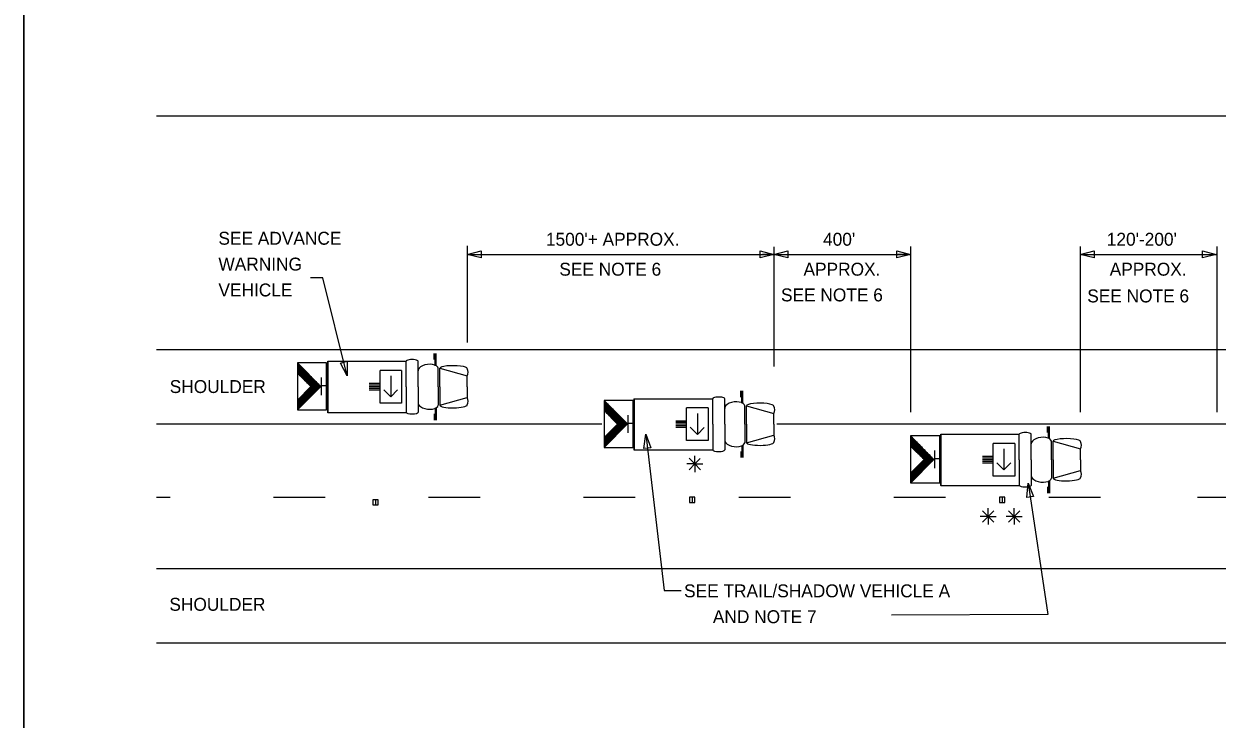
# Model space of a CAD drawing. Extents: x 1416408 to 1429341, y 372694 to 383211.
# Drawn here: x 1426235 to 1427162, y 373399 to 373939 of the extents above; entities that cross this region are included whole.
import ezdxf

# ---------------------------------------------------------------- set-up
doc = ezdxf.new("R2010")
doc.units = 0
for name, color, linetype in [('Default', 7, 'Continuous'), ('DSN_DRFT_Junk-No-Plot', 7, 'Continuous'), ('Level 1', 7, 'Continuous'), ('Working Level 1', 7, 'Continuous')]:
    doc.layers.add(name, color=color, linetype=linetype)

msp = doc.modelspace()

# ---------------------------------------------------------------- linework, layer by layer
at = {"layer": 'Default'}
for points in [[(1426234.86, 374479.9), (1426234.86, 372693.86), (1428995.11, 372693.86), (1428995.11, 374479.9)], [(1426234.86, 374479.9), (1426234.86, 372693.86), (1428995.11, 372693.86), (1428995.11, 374479.9)], [(1426234.86, 374479.9), (1428995.11, 374479.9), (1428995.11, 372693.86), (1426234.86, 372693.86)], [(1426234.86, 374479.9), (1426234.86, 372693.86), (1428995.11, 372693.86), (1428995.11, 374479.9)]]:
    msp.add_lwpolyline(points, close=True, dxfattribs=at)
at = {"layer": 'DSN_DRFT_Junk-No-Plot'}
msp.add_lwpolyline([(1426234.86, 374479.9), (1428995.11, 374479.9), (1428995.11, 372693.86), (1426234.86, 372693.86)], close=True, dxfattribs=at)
at = {"layer": 'Level 1'}
msp.add_lwpolyline([(1427015.28, 373582.25), (1427030.51, 373480.04), (1426909.15, 373479.57)], dxfattribs=at)
at = {"layer": 'Working Level 1'}
for p, q in [((1426337.99, 373867.74), (1427662.99, 373867.74)), ((1426579.46, 373766.82), (1426579.46, 373691.51)), ((1426817.73, 373765.82), (1426817.73, 373672.98)), ((1426923.95, 373766.22), (1426923.95, 373637.48)), ((1427055.68, 373766.22), (1427055.68, 373637.48)), ((1427161.91, 373766.22), (1427161.91, 373637.48)), ((1426579.46, 373760.03), (1426588.68, 373760.03)), ((1426579.46, 373760.03), (1426817.73, 373760.03)), ((1426817.73, 373760.03), (1426808.97, 373760.03)), ((1426817.73, 373760.03), (1426827.96, 373760.03)), ((1426817.73, 373760.03), (1426923.95, 373760.03)), ((1426922.75, 373760.03), (1426913.99, 373760.03)), ((1427055.68, 373760.03), (1427065.92, 373760.03)), ((1427055.68, 373760.03), (1427161.91, 373760.03)), ((1426337.99, 373686), (1427662.99, 373686)), ((1426553.8, 373678.2), (1426553.8, 373683.07)), ((1426554.56, 373673.51), (1426554.56, 373683.07)), ((1426555.21, 373673.51), (1426555.21, 373683.07)), ((1426447.43, 373675.71), (1426465.57, 373657.38)), ((1426470.79, 373676.56), (1426470.79, 373636.76)), ((1426470.95, 373677.02), (1426470.95, 373637.22)), ((1426470.95, 373637.21), (1426470.95, 373677.01)), ((1426470.95, 373677.01), (1426531.88, 373677.01)), ((1426531.88, 373657.11), (1426531.88, 373677.01)), ((1426541.21, 373657.11), (1426541.21, 373677.01)), ((1426447.43, 373667.75), (1426457.83, 373657.27)), ((1426466.18, 373650.48), (1426466.18, 373664.28)), ((1426528.3, 373669.85), (1426511.65, 373669.85)), ((1426511.65, 373644.37), (1426511.65, 373669.85)), ((1426519.98, 373665.52), (1426519.98, 373649.23)), ((1426528.3, 373669.85), (1426528.3, 373644.37)), ((1426556.86, 373657.11), (1426556.86, 373671.45)), ((1426558.16, 373671.45), (1426579.46, 373665.55)), ((1426558.16, 373657.11), (1426558.16, 373671.45)), ((1426579.46, 373657.11), (1426579.46, 373665.55)), ((1426447.43, 373646.78), (1426457.83, 373657.27)), ((1426447.53, 373639.13), (1426465.57, 373657.38)), ((1426469.98, 373657.71), (1426466.08, 373657.71)), ((1426511.65, 373659.65), (1426503.16, 373659.65)), ((1426511.65, 373658.38), (1426503.16, 373658.38)), ((1426511.65, 373657.1), (1426503.16, 373657.1)), ((1426511.65, 373655.83), (1426503.16, 373655.83)), ((1426511.65, 373654.56), (1426503.16, 373654.56)), ((1426519.98, 373649.23), (1426514.5, 373654.77)), ((1426519.98, 373649.23), (1426525.33, 373654.63)), ((1426531.88, 373657.11), (1426531.88, 373637.22)), ((1426541.21, 373657.11), (1426541.21, 373637.22)), ((1426556.86, 373657.11), (1426556.86, 373642.78)), ((1426558.16, 373657.11), (1426558.16, 373642.78)), ((1426579.46, 373657.11), (1426579.46, 373648.67)), ((1426792.06, 373649.04), (1426792.06, 373653.92)), ((1426792.83, 373644.36), (1426792.83, 373653.92)), ((1426793.48, 373644.36), (1426793.48, 373653.92)), ((1426528.3, 373644.37), (1426511.65, 373644.37)), ((1426558.16, 373642.78), (1426579.46, 373648.67)), ((1426685.69, 373646.56), (1426703.84, 373628.23)), ((1426709.05, 373647.4), (1426709.05, 373607.6)), ((1426709.21, 373647.86), (1426709.21, 373608.06)), ((1426709.21, 373608.05), (1426709.21, 373647.85)), ((1426709.21, 373647.85), (1426770.14, 373647.85)), ((1426770.14, 373627.96), (1426770.14, 373647.85)), ((1426779.48, 373627.96), (1426779.48, 373647.85)), ((1426470.95, 373637.22), (1426531.88, 373637.22)), ((1426553.8, 373636.02), (1426553.8, 373631.15)), ((1426554.56, 373640.71), (1426554.56, 373631.15)), ((1426555.21, 373640.71), (1426555.21, 373631.15)), ((1426685.69, 373638.6), (1426696.09, 373628.11)), ((1426704.45, 373621.33), (1426704.45, 373635.13)), ((1426766.57, 373640.69), (1426749.91, 373640.69)), ((1426749.91, 373615.22), (1426749.91, 373640.69)), ((1426758.24, 373636.37), (1426758.24, 373620.07)), ((1426766.57, 373640.69), (1426766.57, 373615.22)), ((1426795.12, 373627.96), (1426795.12, 373642.29)), ((1426796.42, 373642.29), (1426817.72, 373636.4)), ((1426796.42, 373627.96), (1426796.42, 373642.29)), ((1426817.72, 373627.96), (1426817.72, 373636.4)), ((1426337.99, 373628.26), (1426580.23, 373628.26)), ((1426579.86, 373628.26), (1426684.12, 373628.26)), ((1426685.69, 373617.63), (1426696.09, 373628.11)), ((1426685.79, 373609.97), (1426703.84, 373628.23)), ((1426708.24, 373628.56), (1426704.34, 373628.56)), ((1426749.91, 373630.49), (1426741.43, 373630.49)), ((1426749.91, 373629.22), (1426741.43, 373629.22)), ((1426749.91, 373627.95), (1426741.43, 373627.95)), ((1426749.91, 373626.68), (1426741.43, 373626.68)), ((1426758.24, 373620.07), (1426752.76, 373625.61)), ((1426770.14, 373627.96), (1426770.14, 373608.06)), ((1426779.48, 373627.96), (1426779.48, 373608.06)), ((1426795.12, 373627.96), (1426795.12, 373613.62)), ((1426796.42, 373627.96), (1426796.42, 373613.62)), ((1426817.72, 373627.96), (1426817.72, 373619.51)), ((1426819.89, 373628.26), (1427662.99, 373628.26)), ((1427030.33, 373621.45), (1427030.33, 373626.33)), ((1427031.09, 373616.77), (1427031.09, 373626.33)), ((1427031.74, 373616.77), (1427031.74, 373626.33)), ((1426749.91, 373625.41), (1426741.43, 373625.41)), ((1426758.24, 373620.07), (1426763.59, 373625.48)), ((1426796.42, 373613.62), (1426817.72, 373619.51)), ((1426923.95, 373618.97), (1426942.1, 373600.64)), ((1426947.32, 373619.81), (1426947.32, 373580.01)), ((1426947.47, 373620.27), (1426947.47, 373580.47)), ((1426947.47, 373580.46), (1426947.47, 373620.26)), ((1426947.47, 373620.26), (1427008.41, 373620.26)), ((1427008.41, 373600.37), (1427008.41, 373620.26)), ((1427017.74, 373600.37), (1427017.74, 373620.26)), ((1426709.21, 373608.06), (1426770.14, 373608.06)), ((1426766.57, 373615.22), (1426749.91, 373615.22)), ((1426792.83, 373611.56), (1426792.83, 373602)), ((1426793.48, 373611.56), (1426793.48, 373602)), ((1426923.95, 373611.01), (1426934.36, 373600.52)), ((1426942.71, 373593.74), (1426942.71, 373607.54)), ((1427004.83, 373613.1), (1426988.18, 373613.1)), ((1426988.18, 373587.62), (1426988.18, 373613.1)), ((1426996.5, 373608.78), (1426996.5, 373592.48)), ((1427004.83, 373613.1), (1427004.83, 373587.62)), ((1427033.39, 373600.37), (1427033.39, 373614.7)), ((1427034.68, 373614.7), (1427055.99, 373608.81)), ((1427034.68, 373600.37), (1427034.68, 373614.7)), ((1427055.99, 373600.37), (1427055.99, 373608.81)), ((1426756.17, 373597.09), (1426751.77, 373601.54)), ((1426756.07, 373597), (1426760.48, 373601.46)), ((1426756.17, 373597.09), (1426756.17, 373603.39)), ((1426792.06, 373606.86), (1426792.06, 373602)), ((1426923.95, 373590.04), (1426934.36, 373600.52)), ((1426924.05, 373582.38), (1426942.1, 373600.64)), ((1426946.51, 373600.96), (1426942.6, 373600.96)), ((1426988.18, 373602.9), (1426979.69, 373602.9)), ((1426988.18, 373601.63), (1426979.69, 373601.63)), ((1426988.18, 373600.36), (1426979.69, 373600.36)), ((1426988.18, 373599.09), (1426979.69, 373599.09)), ((1426988.18, 373597.81), (1426979.69, 373597.81)), ((1426996.5, 373592.48), (1426991.02, 373598.02)), ((1426996.5, 373592.48), (1427001.85, 373597.89)), ((1427008.41, 373600.37), (1427008.41, 373580.47)), ((1427017.74, 373600.37), (1427017.74, 373580.47)), ((1427033.39, 373600.37), (1427033.39, 373586.03)), ((1427034.68, 373600.37), (1427034.68, 373586.03)), ((1427055.99, 373600.37), (1427055.99, 373591.92)), ((1426756.17, 373597.09), (1426749.94, 373597.09)), ((1426756.17, 373597.09), (1426751.77, 373592.63)), ((1426756.17, 373597.09), (1426760.58, 373592.63)), ((1426756.17, 373597.09), (1426756.17, 373590.79)), ((1426756.17, 373597.09), (1426762.4, 373597.09)), ((1427034.68, 373586.03), (1427055.99, 373591.92)), ((1426947.47, 373580.47), (1427008.41, 373580.47)), ((1427004.83, 373587.62), (1426988.18, 373587.62)), ((1427030.33, 373579.27), (1427030.33, 373574.41)), ((1427031.09, 373583.96), (1427031.09, 373574.41)), ((1427031.74, 373583.96), (1427031.74, 373574.41)), ((1426752.12, 373571.3), (1426752.11, 373567.23)), ((1426756.14, 373571.3), (1426752.12, 373571.3)), ((1426754.14, 373571.3), (1426754.13, 373567.23)), ((1426756.14, 373567.23), (1426756.14, 373571.3)), ((1426993.05, 373571.3), (1426993.04, 373567.23)), ((1426997.07, 373571.3), (1426993.05, 373571.3)), ((1426995.07, 373571.3), (1426995.06, 373567.23)), ((1426997.07, 373567.23), (1426997.07, 373571.3)), ((1426506.12, 373569.27), (1426506.11, 373565.2)), ((1426506.11, 373565.2), (1426510.13, 373565.2)), ((1426510.13, 373569.27), (1426506.12, 373569.27)), ((1426508.13, 373569.27), (1426508.12, 373565.2)), ((1426510.13, 373565.2), (1426510.13, 373569.27)), ((1426752.11, 373567.23), (1426756.14, 373567.23)), ((1426984.25, 373556.31), (1426979.84, 373560.76)), ((1426984.25, 373556.31), (1426984.25, 373562.61)), ((1426993.04, 373567.23), (1426997.07, 373567.23)), ((1427004.41, 373556.31), (1427000, 373560.76)), ((1427004.41, 373556.31), (1427004.41, 373562.61)), ((1426984.25, 373556.31), (1426978.01, 373556.31)), ((1426984.25, 373556.31), (1426979.84, 373551.85)), ((1426984.14, 373556.22), (1426988.56, 373560.68)), ((1426984.25, 373556.31), (1426988.66, 373551.85)), ((1426984.25, 373556.31), (1426984.25, 373550.01)), ((1426984.25, 373556.31), (1426990.48, 373556.31)), ((1427004.41, 373556.31), (1426998.17, 373556.31)), ((1427004.41, 373556.31), (1427000, 373551.85)), ((1427004.3, 373556.22), (1427008.71, 373560.68)), ((1427004.41, 373556.31), (1427008.81, 373551.85)), ((1427004.41, 373556.31), (1427004.41, 373550.01)), ((1427004.41, 373556.31), (1427010.64, 373556.31)), ((1426337.99, 373515.71), (1427411.75, 373515.71)), ((1426337.99, 373457.97), (1427350.68, 373457.97))]:
    msp.add_line(p, q, dxfattribs=at)
for points in [[(1426590.21, 373757.31), (1426579.44, 373760.03), (1426590.21, 373762.75)], [(1426806.96, 373762.75), (1426817.73, 373760.03), (1426806.96, 373757.31)], [(1426828.49, 373757.31), (1426817.73, 373760.03), (1426828.49, 373762.75)], [(1426913.19, 373762.75), (1426923.95, 373760.03), (1426913.19, 373757.31)], [(1427066.45, 373757.31), (1427055.68, 373760.03), (1427066.45, 373762.75)], [(1427150.7, 373762.75), (1427161.46, 373760.03), (1427150.7, 373757.31)], [(1426447.43, 373675.71), (1426447.43, 373639.12), (1426470.05, 373639.12), (1426470.05, 373675.71)], [(1426486.18, 373676.92), (1426486.22, 373665.7), (1426480.96, 373675.58)], [(1426685.69, 373646.56), (1426685.69, 373609.96), (1426708.31, 373609.96), (1426708.31, 373646.56)], [(1426716.75, 373609.03), (1426718.15, 373620.16), (1426722.1, 373609.67)], [(1426923.95, 373618.97), (1426923.95, 373582.37), (1426946.57, 373582.37), (1426946.57, 373618.97)], [(1427014.23, 373571.09), (1427015.28, 373582.25), (1427019.55, 373571.9)]]:
    msp.add_lwpolyline(points, close=True, dxfattribs=at)
for points in [[(1426486.22, 373665.7), (1426467.12, 373741.78), (1426457.57, 373741.78)], [(1426447.43, 373674.85), (1426457, 373658.09)], [(1426447.43, 373673.41), (1426455.11, 373659.96)], [(1426447.43, 373671.97), (1426453.21, 373661.84)], [(1426448.24, 373674.91), (1426460.91, 373652.69)], [(1426450.17, 373672.93), (1426461.44, 373653.21)], [(1426447.43, 373670.53), (1426451.32, 373663.72)], [(1426447.43, 373669.08), (1426449.43, 373665.6)], [(1426447.43, 373667.64), (1426447.53, 373667.48)], [(1426452.12, 373670.98), (1426461.96, 373653.75)], [(1426454.07, 373669), (1426462.48, 373654.26)], [(1426456.01, 373667.04), (1426463, 373654.8)], [(1426457.95, 373665.06), (1426463.55, 373655.29)], [(1426459.9, 373663.1), (1426464.08, 373655.79)], [(1426454.46, 373653.89), (1426457.25, 373649.01)], [(1426454.98, 373654.4), (1426457.78, 373649.53)], [(1426455.51, 373654.95), (1426458.3, 373650.06)], [(1426456.03, 373655.47), (1426458.82, 373650.59)], [(1426456.56, 373655.99), (1426459.34, 373651.11)], [(1426457.07, 373656.53), (1426459.88, 373651.64)], [(1426457.61, 373657.05), (1426460.4, 373652.16)], [(1426461.86, 373661.16), (1426464.56, 373656.4)], [(1426463.65, 373659.36), (1426465.05, 373656.91)], [(1426447.43, 373646.01), (1426449.93, 373641.63)], [(1426447.43, 373644.56), (1426449.4, 373641.1)], [(1426447.67, 373647.03), (1426450.45, 373642.17)], [(1426448.2, 373647.56), (1426450.98, 373642.68)], [(1426448.72, 373648.08), (1426451.49, 373643.21)], [(1426449.25, 373648.62), (1426452.02, 373643.73)], [(1426449.76, 373649.14), (1426452.54, 373644.27)], [(1426450.29, 373649.66), (1426453.06, 373644.79)], [(1426450.8, 373650.19), (1426453.59, 373645.31)], [(1426451.33, 373650.72), (1426454.12, 373645.84)], [(1426451.86, 373651.25), (1426454.63, 373646.36)], [(1426452.38, 373651.78), (1426455.16, 373646.9)], [(1426452.9, 373652.31), (1426455.68, 373647.42)], [(1426453.41, 373652.83), (1426456.2, 373647.95)], [(1426453.95, 373653.36), (1426456.74, 373648.46)], [(1426685.69, 373645.7), (1426695.27, 373628.93)], [(1426685.69, 373644.26), (1426693.37, 373630.8)], [(1426686.5, 373645.75), (1426699.17, 373623.53)], [(1426447.43, 373643.12), (1426448.88, 373640.58)], [(1426447.43, 373641.67), (1426448.36, 373640.05)], [(1426447.43, 373640.23), (1426447.83, 373639.54)], [(1426685.69, 373642.82), (1426691.48, 373632.68)], [(1426685.69, 373641.37), (1426689.58, 373634.57)], [(1426685.69, 373639.93), (1426687.69, 373636.45)], [(1426685.69, 373638.48), (1426685.79, 373638.33)], [(1426688.43, 373643.78), (1426699.7, 373624.06)], [(1426690.38, 373641.82), (1426700.23, 373624.59)], [(1426692.33, 373639.85), (1426700.74, 373625.11)], [(1426694.27, 373637.88), (1426701.26, 373625.64)], [(1426696.22, 373635.91), (1426701.81, 373626.14)], [(1426693.77, 373625.79), (1426696.57, 373620.9)], [(1426694.29, 373626.32), (1426697.08, 373621.43)], [(1426694.82, 373626.83), (1426697.6, 373621.95)], [(1426695.33, 373627.37), (1426698.14, 373622.48)], [(1426695.87, 373627.9), (1426698.66, 373623.01)], [(1426698.16, 373633.95), (1426702.34, 373626.64)], [(1426700.12, 373632), (1426702.82, 373627.24)], [(1426701.91, 373630.2), (1426703.31, 373627.75)], [(1426685.69, 373616.86), (1426688.19, 373612.47)], [(1426685.93, 373617.87), (1426688.71, 373613.02)], [(1426686.46, 373618.41), (1426689.24, 373613.52)], [(1426686.98, 373618.92), (1426689.75, 373614.06)], [(1426687.51, 373619.47), (1426690.28, 373614.58)], [(1426688.02, 373619.98), (1426690.8, 373615.12)], [(1426688.55, 373620.51), (1426691.32, 373615.63)], [(1426689.07, 373621.03), (1426691.85, 373616.16)], [(1426689.59, 373621.57), (1426692.38, 373616.68)], [(1426690.12, 373622.09), (1426692.9, 373617.21)], [(1426690.64, 373622.62), (1426693.42, 373617.74)], [(1426691.16, 373623.16), (1426693.94, 373618.27)], [(1426691.67, 373623.67), (1426694.46, 373618.79)], [(1426692.21, 373624.21), (1426695, 373619.31)], [(1426692.73, 373624.73), (1426695.51, 373619.85)], [(1426693.25, 373625.25), (1426696.04, 373620.38)], [(1426718.15, 373620.16), (1426732.44, 373498.61), (1426745.53, 373498.61)], [(1426923.95, 373618.1), (1426933.53, 373601.34)], [(1426923.95, 373616.67), (1426931.63, 373603.21)], [(1426924.76, 373618.16), (1426937.43, 373595.94)], [(1426685.69, 373615.4), (1426687.66, 373611.95)], [(1426685.69, 373613.97), (1426687.14, 373611.42)], [(1426685.69, 373612.52), (1426686.62, 373610.9)], [(1426685.69, 373611.08), (1426686.09, 373610.38)], [(1426923.95, 373615.22), (1426929.74, 373605.09)], [(1426923.95, 373613.78), (1426927.84, 373606.98)], [(1426923.95, 373612.34), (1426925.95, 373608.86)], [(1426923.95, 373610.89), (1426924.05, 373610.74)], [(1426926.7, 373616.18), (1426937.96, 373596.47)], [(1426928.64, 373614.23), (1426938.49, 373597)], [(1426930.59, 373612.25), (1426939.01, 373597.52)], [(1426932.53, 373610.29), (1426939.53, 373598.05)], [(1426934.48, 373608.32), (1426940.07, 373598.54)], [(1426932.04, 373598.2), (1426934.83, 373593.31)], [(1426932.56, 373598.72), (1426935.35, 373593.84)], [(1426933.08, 373599.24), (1426935.87, 373594.36)], [(1426933.59, 373599.78), (1426936.4, 373594.89)], [(1426934.13, 373600.31), (1426936.92, 373595.42)], [(1426936.43, 373606.36), (1426940.61, 373599.04)], [(1426938.38, 373604.41), (1426941.08, 373599.65)], [(1426940.18, 373602.61), (1426941.57, 373600.16)], [(1426923.95, 373589.27), (1426926.45, 373584.88)], [(1426924.2, 373590.28), (1426926.97, 373585.43)], [(1426924.72, 373590.82), (1426927.5, 373585.93)], [(1426925.24, 373591.33), (1426928.01, 373586.47)], [(1426925.77, 373591.87), (1426928.55, 373586.98)], [(1426926.28, 373592.39), (1426929.07, 373587.53)], [(1426926.81, 373592.92), (1426929.59, 373588.04)], [(1426927.33, 373593.44), (1426930.11, 373588.57)], [(1426927.86, 373593.97), (1426930.64, 373589.09)], [(1426928.38, 373594.5), (1426931.16, 373589.62)], [(1426928.9, 373595.03), (1426931.69, 373590.15)], [(1426929.42, 373595.57), (1426932.21, 373590.68)], [(1426929.93, 373596.08), (1426932.73, 373591.2)], [(1426930.47, 373596.62), (1426933.26, 373591.72)], [(1426930.99, 373597.14), (1426933.77, 373592.26)], [(1426931.51, 373597.66), (1426934.3, 373592.78)], [(1426923.95, 373587.81), (1426925.93, 373584.36)], [(1426923.95, 373586.38), (1426925.41, 373583.83)], [(1426923.95, 373584.92), (1426924.89, 373583.31)], [(1426923.95, 373583.49), (1426924.35, 373582.79)], [(1426337.99, 373571.35), (1426348.54, 373571.35)], [(1426428.86, 373571.35), (1426469.03, 373571.35)], [(1426549.35, 373571.35), (1426589.51, 373571.35)], [(1426669.84, 373571.35), (1426710.01, 373571.35)], [(1426790.33, 373571.35), (1426830.5, 373571.35)], [(1426910.82, 373571.35), (1426950.99, 373571.35)], [(1427031.31, 373571.35), (1427071.48, 373571.35)], [(1427146.83, 373571.35), (1427187, 373571.35)]]:
    msp.add_lwpolyline(points, dxfattribs=at)
for centre, major_axis, ratio, start_param, end_param in [((1426536.55, 373677.01), (4.67, 0), 0.27289, 6.283185, 9.424778), ((1426549.04, 373670.47), (7.82, 0.99), 0.50847, 6.28135, 9.422943), ((1426568.81, 373671.32), (10.65, -0.12), 0.205643, 0.000054, 3.141647), ((1426574.25, 373668.37), (0, 5.98), 0.989089, 4.221603, 5.203174), ((1426549.04, 373643.76), (7.82, -0.99), 0.50847, 3.143427, 6.28502), ((1426574.25, 373645.85), (0, 5.98), 0.989089, 4.221604, 5.203174), ((1426774.81, 373647.85), (4.67, 0), 0.27289, 6.283185, 9.424778), ((1426787.3, 373641.31), (7.82, 0.99), 0.50847, 6.28135, 9.422943), ((1426807.07, 373642.17), (10.65, -0.12), 0.205643, 0.000054, 3.141647), ((1426536.55, 373637.22), (4.67, 0), 0.27289, 3.141593, 6.283185), ((1426568.81, 373642.9), (10.65, 0.12), 0.205643, 3.141539, 6.283131), ((1426812.51, 373639.22), (0, 5.98), 0.989089, 4.221603, 5.203174), ((1426812.51, 373616.69), (0, 5.98), 0.989089, 4.221604, 5.203174), ((1427013.07, 373620.26), (4.67, 0), 0.27289, 6.283185, 9.424778), ((1427025.56, 373613.72), (7.82, 0.99), 0.50847, 6.28135, 9.422943), ((1427045.34, 373614.58), (10.65, -0.12), 0.205643, 0.000054, 3.141647), ((1426774.81, 373608.06), (4.67, 0), 0.27289, 3.141593, 6.283185), ((1426787.3, 373614.6), (7.82, -0.99), 0.50847, 3.143427, 6.28502), ((1426807.07, 373613.75), (10.65, 0.12), 0.205643, 3.141539, 6.283131), ((1427050.78, 373611.63), (0, 5.98), 0.989089, 4.221603, 5.203174), ((1427050.78, 373589.1), (0, 5.98), 0.989089, 4.221604, 5.203174), ((1427013.07, 373580.47), (4.67, 0), 0.27289, 3.141593, 6.283185), ((1427025.56, 373587.01), (7.82, -0.99), 0.50847, 3.143427, 6.28502), ((1427045.34, 373586.16), (10.65, 0.12), 0.205643, 3.141539, 6.283131)]:
    msp.add_ellipse(centre, major_axis=major_axis, ratio=ratio, start_param=start_param, end_param=end_param, dxfattribs=at)

# ---------------------------------------------------------------- texts
for s, height, p in [('SEE ADVANCE ', 10.0465, (1426386.06, 373767.55)), ("1500'+ APPROX.", 10.0465, (1426640.54, 373766.78)), ("400'", 10.046, (1426855.9, 373766.78)), ("120'-200'", 10.046, (1427076.4, 373766.78)), ('WARNING ', 10.046, (1426386.06, 373747.46)), ('SEE NOTE 6', 10.046, (1426650.98, 373743.49)), ('APPROX.', 10.046, (1426840.72, 373743.49)), ('APPROX.', 10.046, (1427078.67, 373743.49)), ('VEHICLE', 10.046, (1426386.06, 373727.36)), ('SEE NOTE 6', 10.046, (1426823.23, 373723.5)), ('SEE NOTE 6', 10.046, (1427061.19, 373722.7)), ('SEE TRAIL/SHADOW VEHICLE A ', 10.0465, (1426747.89, 373493.4)), ('      AND NOTE 7', 10.0465, (1426747.89, 373473.31))]:
    msp.add_text(s, height=height, dxfattribs=at).set_placement(p)
for p in [(1426348.21, 373652.25), (1426347.95, 373482.93)]:
    msp.add_text('SHOULDER', height=10.046, rotation=0, dxfattribs=at).set_placement(p)

doc.saveas('drawing.dxf')
